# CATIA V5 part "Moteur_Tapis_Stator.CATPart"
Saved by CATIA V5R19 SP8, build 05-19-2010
Part number: Moteur_Tapis_Stator
Nomenclature: 69-a
Bounding box of the stored display mesh (mm): x -158 to 30, y -60 to 60, z -53.548 to 53.548
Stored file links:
  C:\Users\rphgr\Desktop\0_Tapis_TC520B_vitesse\Moteur_Tapis_Stator.CATPart
  D:\Programmes\DassaultSysteme\win_b64\reffiles\standard\MetricThickPitch.txt
  D:\Documents\1_Travail\1 - ac-limoges.fr\ac-limoges.fr\Emmanuel Maynard - STI2D_Turgot\3 - Supports\Tapis de course TC520B\Tapis de course TC520B_Ca\0_Tapis_TC520B.CATProduct
  D:\Documents\1_Travail\1 - ac-limoges.fr\ac-limoges.fr\Emmanuel Maynard - STI2D_Turgot\3 - Supports\Tapis de course TC520B\Tapis de course TC520B_Ca\Cadre Chasis (1).CATPart
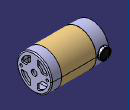
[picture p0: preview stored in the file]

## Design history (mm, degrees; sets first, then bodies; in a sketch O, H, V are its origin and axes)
AxisSystem1: origin (0, 0, 0), X (1, 0, 0), Y (0, 1, 0), Z (0, 0, 1)
Body1 (main body)
  Sketch1 on YZ plane of AxisSystem1, origin (0, 0, 0), H (0, 1, 0), V (0, 0, 1)
    circle A1 centre (0, 0) radius 52.5
    radius A1 = 52.5
  Pad1: profile Sketch1, direction (1, 0, 0), length 30, opposite side up to YZ plane of AxisSystem1
  Fillet1: radius 0.3, on edge [face of Pad1 | face of Pad1 from Sketch1.A1]
  Draft1: PullDir end face of Pad1, Angle 2, SupportToDraft face of Pad1 from Sketch1.A1, Neutral end face of Pad1
  Fillet2: radius 3, on edge [face of Pad1 from Sketch1.A1 | end face of Pad1]
  Shell1: IntOffset 5, Face face of Pad1, ExtOffset 0
  Sketch2 on face of Pad1, origin (0, 0, 0), H (0, -1, 0), V (0, 0, 1)
    projected circle E1 centre (0, 0) radius 53.5476 from edge [face of Pad1 from Sketch1.A1 | face of Pad1]
    projected circle E2 centre (0, 0) radius 48.5446 from edge [face of Shell1 | face of Pad1]
  Pad2: profile Sketch2, direction (-1, 0, 0), length 106
  Fillet3: radius 0.5, on end face of Pad2
  Sketch3 on end face of Pad2, origin (-106, 0, 0), H (0, -1, 0), V (0, 0, 1)
    projected circle E1 centre (0, 0) radius 53.5476 from edge [face of Pad2 from Sketch2.E1 | face of Fillet3]
  Pad3: profile Sketch3, direction (-1, 0, 0), length 40
  Draft2: PullDir end face of Pad1, Angle -2, SupportToDraft face of Pad3 from Sketch3.E1, Neutral start face of Pad3
  Fillet4: radius 1, on edge [face of Pad3 from Sketch3.E1 | end face of Pad3]
  Sketch4 on {plane type Offset, RefPlane xy-plane, Offset 52.5, reversed}, origin (-10.761, 77.1772, -52.5), H (1, 0, 0), V (0, 1, 0)
    point P1 (-75.239, -77.1772)
    reference projected line E1 through (0, -77.1772) direction (-1, 0) from axis of face of Pad2 from Sketch2.E1
    reference intersected line E2 (-95.239, -66.6369) -> (-95.239, -87.7175) from start face of Pad3
    distance P1 E2 = 20
    coincidence: P1 E1
  Hole1: placed by Sketch4, at (-86, 0, -52.5) direction (0, 0, -1), diameter 6.647, depth 10, threaded "M8", thread diameter 8, thread depth 10, pitch 1.25
  Sketch5 on {plane type Offset, RefPlane xy-plane, Offset 52.5, reversed}, origin (-34.8079, -0.0472, -52.5), H (1, 0, 0), V (0, 1, 0)
    point P1 (13.8079, 0.0472)
    reference projected point E1 (-51.1921, 0.0472) from axis of face of Hole1
    reference projected line E2 through (0, 0.0472) direction (1, 0) from edge [XY plane of AxisSystem1 | ZX plane of AxisSystem1]
    distance E1 P1 = 65
    coincidence: P1 E2
  Hole2: placed by Sketch5, at (-21, 0, -52.5) direction (0, 0, -1), diameter 6.647, depth 10, threaded "M8", thread diameter 8, thread depth 10, pitch 1.25
  Sketch6 on end face of Pad1, origin (30, 0, 0), H (0, 1, 0), V (0, 0, 1)
    arc A1 centre (0, 0) radius 42 from (-10, 40.7922) to (-40.7922, 10) ccw
    arc A2 centre (0, 0) radius 25 from (-10, 22.9129) to (-22.9129, 10) ccw
    line L1 (40.7922, -10) -> (22.9129, -10)
    line L2 (-40.7922, 10) -> (-22.9129, 10)
    line L3 (10, 40.7922) -> (10, 22.9129)
    line L4 (-10, -40.7922) -> (-10, -22.9129)
    point P4 (-10, 22.9129)
    line L5 (10, -22.9129) -> (10, -40.7922)
    line L6 (-10, 22.9129) -> (-10, 40.7922)
    line L7 (22.9129, 10) -> (40.7922, 10)
    point P6 (22.9129, 10)
    line L8 (-22.9129, -10) -> (-40.7922, -10)
    point P8 (-22.9129, -10)
    point P9 (22.9129, -10)
    point P10 (10, -22.9129)
    arc A3 centre (0, 0) radius 25 from (10, -22.9129) to (22.9129, -10) ccw
    arc A4 centre (0, 0) radius 25 from (22.9129, 10) to (10, 22.9129) ccw
    arc A5 centre (0, 0) radius 25 from (-22.9129, -10) to (-10, -22.9129) ccw
    point P12 (-40.7922, -10)
    arc A6 centre (0, 0) radius 42 from (-40.7922, -10) to (-10, -40.7922) ccw
    point P14 (10, -40.7922)
    arc A7 centre (0, 0) radius 42 from (10, -40.7922) to (40.7922, -10) ccw
    arc A8 centre (0, 0) radius 42 from (40.7922, 10) to (10, 40.7922) ccw
    radius A2 = 25
    distance A2 A1 = 17
    distance L3 L4 = 20
    distance L2 L1 = 20
    horizontal: L1 H, L2 H, L7 H, L8 H
    equidistance: L1 L2 O, L3 L4 O
    vertical: L3 V, L4 V, L5 V, L6 V
    coincidence: L4 P4, L3 L5, L4 L6, A2 P6, L1 L8, A2 P8, A2 P9, A2 P10, A2 A3, A3 A4, A2 A5, A1 P12, A1 A6, A6 P14, A6 A7, A7 A8, L7 L2
  Pocket1: profile Sketch6, direction (-1, 0, 0), length 58
  Sketch7 on start face of Pad3, origin (-106, 0, 0), H (0, 1, 0), V (0, 0, 1)
    circle A1 centre (0, 0) radius 48.5476
    reference projected point E1 (0, 0) from axis of face of Pad2 from Sketch2.E1
    reference projected circle E2 centre (0, 0) radius 53.5476 from edge [face of Pad2 from Sketch2.E1 | face of Fillet3]
    distance A1 E2 = 5
    concentricity: A1 E1
  Pocket2: profile Sketch7, direction (-1, 0, 0), up to end face of Pad3, offset -5
  Sketch8 on end face of Pad1, origin (30, 0, 0), H (0, 1, 0), V (0, 0, 1)
    circle A1 centre (-40, 0) radius 4
    point P1 (-40, 0)
    circle A2 centre (40, 0) radius 4
    point P2 (40, 0)
    reference intersected line E1 through (0, 0) direction (0, 1) from ZX plane of AxisSystem1
    circle A3 centre (0, 0) radius 8.5
    radius A2 = 4
    radius A1 = 4
    distance P1 V = 40
    distance P2 E1 = 40
    radius A3 = 8.5
    coincidence: P1 H, P2 H
  Pocket3: profile Sketch8, direction (-1, 0, 0), through (limit type 6)
  Fillet5: radius 3, on edge [face of Pocket1 from Sketch6.L2 | face of Pocket1 from Sketch6.A1]; edge [face of Pocket1 from Sketch6.A1 | face of Pocket1 from Sketch6.L6]; edge [face of Pocket1 from Sketch6.L3 | face of Pocket1 from Sketch6.A8]; edge [face of Pocket1 from Sketch6.A8 | face of Pocket1 from Sketch6.L7]; edge [face of Pocket1 from Sketch6.L1 | face of Pocket1 from Sketch6.A7]; edge [face of Pocket1 from Sketch6.A6 | face of Pocket1 from Sketch6.L8]; edge [face of Pocket1 from Sketch6.L4 | face of Pocket1 from Sketch6.A6]; edge [face of Pocket1 from Sketch6.A7 | face of Pocket1 from Sketch6.L5]; edge [face of Pocket1 from Sketch6.A2 | face of Pocket1 from Sketch6.L2]; edge [face of Pocket1 from Sketch6.L6 | face of Pocket1 from Sketch6.A2]; edge [face of Pocket1 from Sketch6.A4 | face of Pocket1 from Sketch6.L3]; edge [face of Pocket1 from Sketch6.L7 | face of Pocket1 from Sketch6.A4]; edge [face of Pocket1 from Sketch6.A3 | face of Pocket1 from Sketch6.L1]; edge [face of Pocket1 from Sketch6.L5 | face of Pocket1 from Sketch6.A3]; edge [face of Pocket1 from Sketch6.A5 | face of Pocket1 from Sketch6.L4]; edge [face of Pocket1 from Sketch6.L8 | face of Pocket1 from Sketch6.A5]
  Sketch9 on end face of Pad3, origin (-146, 0, 0), H (0, -1, 0), V (0, 0, 1)
    arc A1 centre (0, 0) radius 45 from (-23.0488, 38.6491) to (-38.6491, 23.0488) ccw
    line L1 (-21, 17) -> (-35.2136, 17)
    line L2 (-17, 35.2136) -> (-17, 21)
    arc A2 centre (-21, 21) radius 4 from (-21, 17) to (-17, 21) ccw
    arc A3 centre (-21, 35.2136) radius 4 from (-23.0488, 38.6491) to (-17, 35.2136) cw
    arc A4 centre (-35.2136, 21) radius 4 from (-38.6491, 23.0488) to (-35.2136, 17) ccw
    radius A1 = 45
    distance L2 V = 17
    distance L1 H = 17
    radius A2 = 4
    radius A3 = 4
    radius A4 = 4
    horizontal: L1 H
    vertical: L2 V
    tangency: A2 L1, A2 L2, A3 L2, A3 A1, A4 A1, A4 L1
  Pocket4: profile Sketch9, direction (1, 0, 0), through (limit type 6)
  CircPattern1: of Pocket4, instances 4, angular step 90 {= 360.0*1 deg/CircPattern1.AngularNumber}, axis from face of Pad2 from Sketch2.E1
  Sketch10 on end face of Pad3, origin (-146, 0, 0), H (0, -1, 0), V (0, 0, 1)
    circle A1 centre (0, 0) radius 22
    radius A1 = 22
  Pad4: profile Sketch10, direction (-1, 0, 0), length 12, opposite side up to end face of Pad3
  Draft3: PullDir end face of Pad4, Angle 2, SupportToDraft face of Pad4 from Sketch10.A1, Neutral end face of Pad4
  Fillet6: radius 1, on edge [face of Pad4 from Sketch10.A1 | end face of Pad4]
  Fillet7: radius 1, on edge [face of Pad4 from Sketch10.A1 | end face of Pad3]
  Sketch11 on ZX plane of AxisSystem1, origin (0, 0, 0), H (0, 0, 1), V (1, 0, 0)
    line L1 (30, -146) -> (18.5889, -157.4111)
    point P1 (30, -146)
    reference intersected line E1 (53.5476, -146) -> (-53.5476, -146) from end face of Pad3
    reference intersected line E2 (53.5476, -146) -> (-53.5476, -146) from end face of Pad3
    reference projected line E3 through (0, 0) direction (0, -1) from axis of face of Pad2 from Sketch2.E1
    angle L1 E1 = 45
    distance P1 E3 = 30
    coincidence: P1 E2
  Stiffener1: ThicknessValue 4, ExtendedProfile Sketch11, ThicknessTop 0
  CircPattern2: of Stiffener1, instances 4, angular step 90, axis from face of Pad2 from Sketch2.E1
  Fillet8: radius 0.5, on face of CircPattern2 (x9); face of Stiffener1 from Sketch11.L1; face of Stiffener1 (x2); edge [end face of Pad3 | face of Pocket4 from Sketch9.L1]; edge [end face of Pad3 | face of CircPattern1] (x3)
  Sketch12 on end face of Pad4, origin (-158, 0, 0), H (0, -1, 0), V (0, 0, 1)
    circle A1 centre (0, 0) radius 8.75
    radius A1 = 8.75
  Pocket5: profile Sketch12, direction (1, 0, 0), through (limit type 6)
  Sketch13 on ZX plane of AxisSystem1, origin (0, 0, 0), H (0, 0, 1), V (1, 0, 0)
    circle A1 centre (0, -128) radius 17
    point P1 (0, -128)
    reference intersected line E1 (53.5476, -146) -> (-53.5476, -146) from end face of Pad3
    radius A1 = 17
    distance P1 E1 = 18
    coincidence: P1 V
  Pad5: profile Sketch13, direction (0, 1, 0), length 60, opposite side length -43, thin wall 3.5
  Fillet9: radius 1, on face of Pad3 from Sketch3.E1; edge [face of Pad5 | end face of Pad5]; edge [end face of Pad5 | face of Pad5]; edge [face of Pad3 from Sketch3.E1 | face of Pad5]
  Sketch14 on end face of Pad5, origin (0, 60, 0), H (-1, 0, 0), V (0, 0, 1)
    projected circle E1 centre (128, 0) radius 13.5 from edge [face of Fillet9 | face of Pad5]
  Pad6: profile Sketch14, direction (0, -1, 0), length 5, opposite side length -3
  Mirror1: of Pad5, Fillet9, Pad6, about ZX plane of AxisSystem1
